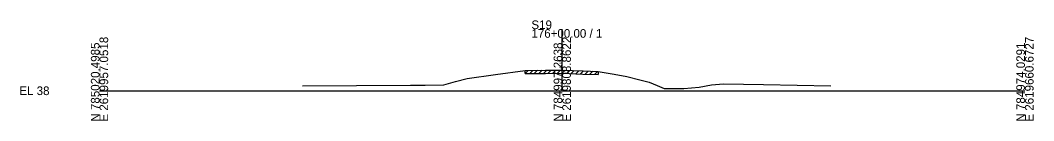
# Model space of a CAD drawing. Extents: x -26 to 1603, y -10 to 5028.
# Drawn here: x -25.7 to 302.8, y 990.3 to 1022.8 of the extents above; entities that cross this region are included whole.
import ezdxf

# ---------------------------------------------------------------- set-up
doc = ezdxf.new("R2010")
doc.units = 0
for name, color, linetype in [('RD_GPK_XS_Cell', 7, 'Continuous'), ('RD_XS_ExGround', 7, 'Continuous'), ('RD_XS_ExPaveRet', 7, 'Continuous'), ('RD_XS_TX_Elev_EX', 7, 'Continuous')]:
    doc.layers.add(name, color=color, linetype=linetype)

msp = doc.modelspace()

# ---------------------------------------------------------------- linework, layer by layer
at = {"layer": 'RD_GPK_XS_Cell'}
for p, q in [((150, 1000), (150, 1019.96)), ((0, 1000), (150, 1000)), ((150, 1000), (300, 1000))]:
    msp.add_line(p, q, dxfattribs=at)
at = {"layer": 'RD_XS_ExGround'}
for p, q in [((128.41, 1005.27), (137.94, 1006.59)), ((137.94, 1006.59), (144.57, 1006.63)), ((144.57, 1006.63), (149.92, 1006.65)), ((149.92, 1006.65), (156.68, 1006.42)), ((156.68, 1006.42), (161.65, 1006.24)), ((161.65, 1006.24), (166.83, 1005.34)), ((166.83, 1005.34), (170.93, 1004.64)), ((111.56, 1001.97), (115.43, 1002.96)), ((115.43, 1002.96), (119.16, 1003.97)), ((119.16, 1003.97), (128.41, 1005.27)), ((170.93, 1004.64), (175.1, 1003.57)), ((175.1, 1003.57), (178.18, 1002.8)), ((178.18, 1002.8), (180.73, 1001.65)), ((198.4, 1001.89), (202.29, 1002.24)), ((202.29, 1002.24), (215.28, 1002.07)), ((215.28, 1002.07), (237.1, 1001.55)), ((65.79, 1001.57), (100.81, 1001.78)), ((100.81, 1001.78), (105.57, 1001.84)), ((105.57, 1001.84), (111.56, 1001.97)), ((180.73, 1001.65), (183.02, 1000.74)), ((183.02, 1000.74), (189.4, 1000.76)), ((189.4, 1000.76), (194.4, 1001.14)), ((194.4, 1001.14), (198.4, 1001.89))]:
    msp.add_line(p, q, dxfattribs=at)
at = {"layer": 'RD_XS_ExPaveRet'}
for p, q in [((137.94, 1005.59), (138.95, 1006.6)), ((137.94, 1005.59), (137.94, 1006.59)), ((137.94, 1005.59), (144.57, 1005.63)), ((139.44, 1005.6), (140.45, 1006.61)), ((140.94, 1005.61), (141.95, 1006.62)), ((142.44, 1005.62), (143.45, 1006.63)), ((143.94, 1005.63), (144.95, 1006.64)), ((144.57, 1005.63), (149.92, 1005.65)), ((145.44, 1005.64), (146.45, 1006.64)), ((146.94, 1005.64), (147.95, 1006.65)), ((148.44, 1005.65), (149.45, 1006.65)), ((149.92, 1005.65), (156.68, 1005.42)), ((149.94, 1005.65), (150.91, 1006.62)), ((151.44, 1005.6), (152.41, 1006.57)), ((152.94, 1005.55), (153.91, 1006.52)), ((154.44, 1005.5), (155.41, 1006.46)), ((155.94, 1005.44), (156.91, 1006.41)), ((156.68, 1005.42), (161.65, 1005.24)), ((157.44, 1005.39), (158.41, 1006.36)), ((158.94, 1005.34), (159.91, 1006.3)), ((160.44, 1005.28), (161.41, 1006.25)), ((161.65, 1006.24), (161.65, 1005.24))]:
    msp.add_line(p, q, dxfattribs=at)

# ---------------------------------------------------------------- texts
at = {"layer": 'RD_GPK_XS_Cell'}
for s, p in [('S19', (140, 1019.96)), ('176+00.00 / 1', (140, 1017.16)), ('EL 38', (-26, 998.6))]:
    msp.add_text(s, height=2.8, dxfattribs=at).set_placement(p)
for s, p in [('N 785020.4985', (0, 990)), ('E 2619957.0518', (2.8, 990)), ('N 784997.2638', (150, 990)), ('E 2619808.8622', (152.8, 990)), ('N 784974.0291', (300, 990)), ('E 2619660.6727', (302.8, 990))]:
    msp.add_text(s, height=2.8, rotation=90, dxfattribs=at).set_placement(p)
at = {"layer": 'RD_XS_TX_Elev_EX'}
msp.add_text('44.65', height=0.8, rotation=90, dxfattribs=at).set_placement((149.9, 1007.09))

doc.saveas('drawing.dxf')
